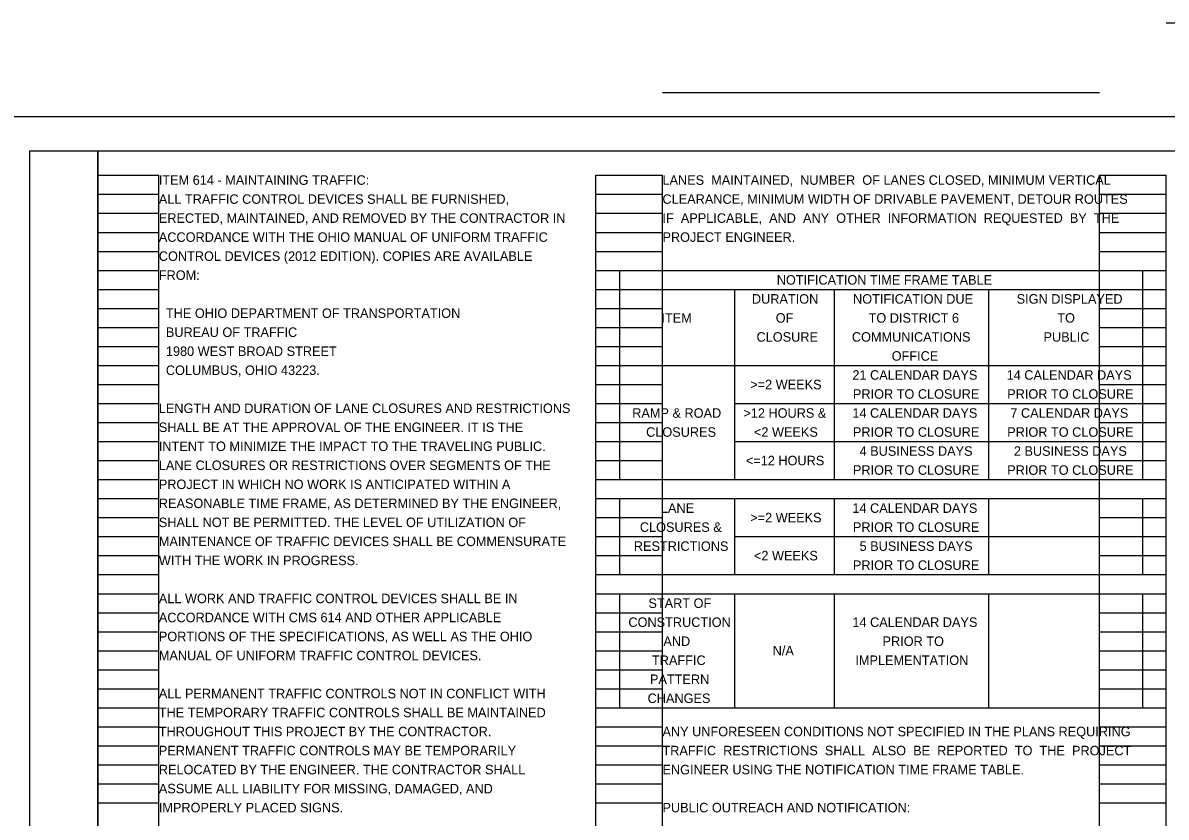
# Model space of a CAD drawing. Extents: x -15.6 to 56.6, y 0 to 56.8.
# Drawn here: x 0.4 to 17.24, y 11.69 to 23.38 of the extents above; entities that cross this region are included whole.
import ezdxf

# ---------------------------------------------------------------- set-up
doc = ezdxf.new("R2010")
doc.units = 0
for name, color, linetype in [('SH_Border', 7, 'Continuous'), ('SH_Cut_Line', 7, 'Continuous'), ('SH_Data', 7, 'Continuous'), ('SH_Text', 7, 'Continuous')]:
    doc.layers.add(name, color=color, linetype=linetype)

msp = doc.modelspace()

# ---------------------------------------------------------------- linework, layer by layer
at = {"layer": 'SH_Border'}
for points in [[(0.5, 21.5), (1.5, 21.5), (1.5, 0.5), (0.5, 0.5)], [(1.5, 21.5), (33.5, 21.5), (33.5, 0.5), (1.5, 0.5)]]:
    msp.add_lwpolyline(points, close=True, dxfattribs=at)
at = {"layer": 'SH_Cut_Line'}
msp.add_lwpolyline([(0, 0), (34, 0), (34, 22), (0, 22)], close=True, dxfattribs=at)
at = {"layer": 'SH_Data'}
for p, q in [((1.5, 0.98), (1.5, 21.14)), ((1.5, 21.14), (2.4, 21.14)), ((2.4, 0.98), (2.4, 21.14)), ((8.84, 0.98), (8.84, 21.14)), ((8.84, 21.14), (9.82, 21.14)), ((9.82, 0.98), (9.82, 21.14)), ((16.26, 0.98), (16.26, 21.14)), ((16.26, 21.14), (17.24, 21.14)), ((17.24, 0.98), (17.24, 21.14)), ((1.5, 20.86), (2.4, 20.86)), ((8.84, 20.86), (9.82, 20.86)), ((16.26, 20.86), (17.24, 20.86)), ((1.5, 20.58), (2.4, 20.58)), ((8.84, 20.58), (9.82, 20.58)), ((16.26, 20.58), (17.24, 20.58)), ((1.5, 20.3), (2.4, 20.3)), ((8.84, 20.3), (9.82, 20.3)), ((16.26, 20.3), (17.24, 20.3)), ((1.5, 20.02), (2.4, 20.02)), ((8.84, 20.02), (9.82, 20.02)), ((16.26, 20.02), (17.24, 20.02)), ((1.5, 19.74), (2.4, 19.74)), ((8.84, 19.74), (9.82, 19.74)), ((16.26, 19.74), (17.24, 19.74)), ((1.5, 19.46), (2.4, 19.46)), ((8.84, 19.46), (9.82, 19.46)), ((16.26, 19.46), (17.24, 19.46)), ((1.5, 19.18), (2.4, 19.18)), ((8.84, 19.18), (9.82, 19.18)), ((16.26, 19.18), (17.24, 19.18)), ((1.5, 18.9), (2.4, 18.9)), ((8.84, 18.9), (9.82, 18.9)), ((16.26, 18.9), (17.24, 18.9)), ((1.5, 18.62), (2.4, 18.62)), ((8.84, 18.62), (9.82, 18.62)), ((16.26, 18.62), (17.24, 18.62)), ((1.5, 18.34), (2.4, 18.34)), ((8.84, 18.34), (9.82, 18.34)), ((16.26, 18.34), (17.24, 18.34)), ((1.5, 18.06), (2.4, 18.06)), ((8.84, 18.06), (9.82, 18.06)), ((16.26, 18.06), (17.24, 18.06)), ((1.5, 17.78), (2.4, 17.78)), ((8.84, 17.78), (9.82, 17.78)), ((16.26, 17.78), (17.24, 17.78)), ((1.5, 17.5), (2.4, 17.5)), ((8.84, 17.5), (9.82, 17.5)), ((16.26, 17.5), (17.24, 17.5)), ((1.5, 17.22), (2.4, 17.22)), ((8.84, 17.22), (9.82, 17.22)), ((16.26, 17.22), (17.24, 17.22)), ((1.5, 16.94), (2.4, 16.94)), ((8.84, 16.94), (9.82, 16.94)), ((16.26, 16.94), (17.24, 16.94)), ((1.5, 16.66), (2.4, 16.66)), ((8.84, 16.66), (9.82, 16.66)), ((16.26, 16.66), (17.24, 16.66)), ((1.5, 16.38), (2.4, 16.38)), ((8.84, 16.38), (9.82, 16.38)), ((16.26, 16.38), (17.24, 16.38)), ((1.5, 16.1), (2.4, 16.1)), ((8.84, 16.1), (9.82, 16.1)), ((16.26, 16.1), (17.24, 16.1)), ((1.5, 15.82), (2.4, 15.82)), ((8.84, 15.82), (9.82, 15.82)), ((16.26, 15.82), (17.24, 15.82)), ((1.5, 15.54), (2.4, 15.54)), ((8.84, 15.54), (9.82, 15.54)), ((16.26, 15.54), (17.24, 15.54)), ((1.5, 15.26), (2.4, 15.26)), ((8.84, 15.26), (9.82, 15.26)), ((16.26, 15.26), (17.24, 15.26)), ((1.5, 14.98), (2.4, 14.98)), ((8.84, 14.98), (9.82, 14.98)), ((16.26, 14.98), (17.24, 14.98)), ((1.5, 14.7), (2.4, 14.7)), ((8.84, 14.7), (9.82, 14.7)), ((16.26, 14.7), (17.24, 14.7)), ((1.5, 14.42), (2.4, 14.42)), ((8.84, 14.42), (9.82, 14.42)), ((16.26, 14.42), (17.24, 14.42)), ((1.5, 14.14), (2.4, 14.14)), ((8.84, 14.14), (9.82, 14.14)), ((16.26, 14.14), (17.24, 14.14)), ((1.5, 13.86), (2.4, 13.86)), ((8.84, 13.86), (9.82, 13.86)), ((16.26, 13.86), (17.24, 13.86)), ((1.5, 13.58), (2.4, 13.58)), ((8.84, 13.58), (9.82, 13.58)), ((16.26, 13.58), (17.24, 13.58)), ((1.5, 13.3), (2.4, 13.3)), ((8.84, 13.3), (9.82, 13.3)), ((16.26, 13.3), (17.24, 13.3)), ((1.5, 13.02), (2.4, 13.02)), ((8.84, 13.02), (9.82, 13.02)), ((16.26, 13.02), (17.24, 13.02)), ((1.5, 12.74), (2.4, 12.74)), ((8.84, 12.74), (9.82, 12.74)), ((16.26, 12.74), (17.24, 12.74)), ((1.5, 12.46), (2.4, 12.46)), ((8.84, 12.46), (9.82, 12.46)), ((16.26, 12.46), (17.24, 12.46)), ((1.5, 12.18), (2.4, 12.18)), ((8.84, 12.18), (9.82, 12.18)), ((16.26, 12.18), (17.24, 12.18)), ((1.5, 11.9), (2.4, 11.9)), ((8.84, 11.9), (9.82, 11.9)), ((16.26, 11.9), (17.24, 11.9))]:
    msp.add_line(p, q, dxfattribs=at)
at = {"layer": 'SH_Text'}
for p, q in [((17.24, 23.384), (23.68, 23.384)), ((9.82, 22.359), (16.26, 22.359)), ((9.186, 19.74), (16.894, 19.74)), ((9.186, 19.74), (9.186, 16.66)), ((16.894, 19.74), (16.894, 16.66)), ((9.186, 19.46), (16.894, 19.46)), ((10.882, 19.46), (10.882, 16.66)), ((12.348, 19.46), (12.348, 16.66)), ((14.621, 19.46), (14.621, 16.66)), ((9.186, 18.34), (16.894, 18.34)), ((10.882, 17.78), (16.894, 17.78)), ((10.882, 17.22), (16.894, 17.22)), ((9.186, 16.66), (16.894, 16.66)), ((9.186, 16.38), (16.894, 16.38)), ((9.186, 16.38), (9.186, 15.26)), ((10.882, 16.38), (10.882, 15.26)), ((12.348, 16.38), (12.348, 15.26)), ((14.621, 16.38), (14.621, 15.26)), ((16.894, 16.38), (16.894, 15.26)), ((10.882, 15.82), (16.894, 15.82)), ((9.186, 15.26), (16.894, 15.26)), ((9.186, 14.98), (16.894, 14.98)), ((9.186, 14.98), (9.186, 13.3)), ((10.882, 14.98), (10.882, 13.3)), ((12.348, 14.98), (12.348, 13.3)), ((14.621, 14.98), (14.621, 13.3)), ((16.894, 14.98), (16.894, 13.3)), ((9.186, 13.3), (16.894, 13.3))]:
    msp.add_line(p, q, dxfattribs=at)

# ---------------------------------------------------------------- texts
for s, p in [('ITEM 614 - MAINTAINING TRAFFIC:', (2.4, 21)), ('LANES  MAINTAINED,  NUMBER  OF LANES CLOSED, MINIMUM VERTICAL', (9.82, 21)), ('ALL TRAFFIC CONTROL DEVICES SHALL BE FURNISHED, ', (2.4, 20.72)), ('CLEARANCE, MINIMUM WIDTH OF DRIVABLE PAVEMENT, DETOUR ROUTES', (9.82, 20.72)), ('ERECTED, MAINTAINED, AND REMOVED BY THE CONTRACTOR IN ', (2.4, 20.44)), ('IF  APPLICABLE,  AND  ANY  OTHER  INFORMATION  REQUESTED  BY  THE', (9.82, 20.44)), ('ACCORDANCE WITH THE OHIO MANUAL OF UNIFORM TRAFFIC ', (2.4, 20.16)), ('PROJECT ENGINEER.', (9.82, 20.16)), ('CONTROL DEVICES (2012 EDITION). COPIES ARE AVAILABLE ', (2.4, 19.88)), ('FROM: ', (2.4, 19.6)), ('NOTIFICATION TIME FRAME TABLE', (11.504, 19.53)), ('DURATION', (11.138, 19.25)), ('NOTIFICATION DUE', (12.628, 19.25)), ('SIGN DISPLAYED', (15.038, 19.25)), ('  THE OHIO DEPARTMENT OF TRANSPORTATION ', (2.4, 19.04)), ('ITEM', (9.805, 18.97)), ('OF', (11.489, 18.97)), ('TO DISTRICT 6', (12.857, 18.97)), ('TO', (15.637, 18.97)), ('  BUREAU OF TRAFFIC', (2.4, 18.76)), ('CLOSURE', (11.206, 18.69)), ('COMMUNICATIONS', (12.611, 18.69)), ('PUBLIC', (15.434, 18.69)), ('  1980 WEST BROAD STREET ', (2.4, 18.48)), (' OFFICE', (13.145, 18.41)), ('  COLUMBUS, OHIO 43223.', (2.4, 18.2)), ('21 CALENDAR DAYS', (12.618, 18.13)), ('14 CALENDAR DAYS', (14.891, 18.13)), ('>=2 WEEKS', (11.113, 17.99)), ('PRIOR TO CLOSURE', (12.626, 17.85)), ('PRIOR TO CLOSURE', (14.899, 17.85)), ('LENGTH AND DURATION OF LANE CLOSURES AND RESTRICTIONS ', (2.4, 17.64)), ('RAMP & ROAD', (9.375, 17.57)), ('>12 HOURS &', (11.012, 17.57)), ('14 CALENDAR DAYS', (12.618, 17.57)), ('7 CALENDAR DAYS', (14.946, 17.57)), ('SHALL BE AT THE APPROVAL OF THE ENGINEER. IT IS THE ', (2.4, 17.36)), ('CLOSURES', (9.579, 17.29)), ('<2 WEEKS', (11.168, 17.29)), ('PRIOR TO CLOSURE', (12.626, 17.29)), ('PRIOR TO CLOSURE', (14.899, 17.29)), ('INTENT TO MINIMIZE THE IMPACT TO THE TRAVELING PUBLIC. ', (2.4, 17.08)), ('<=12 HOURS', (11.049, 16.87)), ('4 BUSINESS DAYS', (12.724, 17.01)), ('2 BUSINESS DAYS', (14.997, 17.01)), ('LANE CLOSURES OR RESTRICTIONS OVER SEGMENTS OF THE ', (2.4, 16.8)), ('PRIOR TO CLOSURE', (12.626, 16.73)), ('PRIOR TO CLOSURE', (14.899, 16.73)), ('PROJECT IN WHICH NO WORK IS ANTICIPATED WITHIN A ', (2.4, 16.52)), ('REASONABLE TIME FRAME, AS DETERMINED BY THE ENGINEER, ', (2.4, 16.24)), ('LANE', (9.797, 16.17)), ('>=2 WEEKS', (11.113, 16.03)), ('14 CALENDAR DAYS', (12.618, 16.17)), ('SHALL NOT BE PERMITTED. THE LEVEL OF UTILIZATION OF ', (2.4, 15.96)), ('CLOSURES &', (9.487, 15.89)), ('PRIOR TO CLOSURE', (12.626, 15.89)), ('MAINTENANCE OF TRAFFIC DEVICES SHALL BE COMMENSURATE ', (2.4, 15.68)), ('RESTRICTIONS', (9.398, 15.61)), ('5 BUSINESS DAYS', (12.724, 15.61)), ('WITH THE WORK IN PROGRESS.', (2.4, 15.4)), ('<2 WEEKS', (11.168, 15.47)), ('PRIOR TO CLOSURE', (12.626, 15.33)), ('ALL WORK AND TRAFFIC CONTROL DEVICES SHALL BE IN ', (2.4, 14.84)), ('START OF', (9.613, 14.77)), ('ACCORDANCE WITH CMS 614 AND OTHER APPLICABLE ', (2.4, 14.56)), ('CONSTRUCTION', (9.318, 14.49)), ('14 CALENDAR DAYS', (12.618, 14.49)), ('PORTIONS OF THE SPECIFICATIONS, AS WELL AS THE OHIO ', (2.4, 14.28)), ('AND', (9.833, 14.21)), ('PRIOR TO', (13.062, 14.21)), ('N/A', (11.444, 14.07)), ('MANUAL OF UNIFORM TRAFFIC CONTROL DEVICES.', (2.4, 14)), ('TRAFFIC', (9.666, 13.93)), ('IMPLEMENTATION', (12.662, 13.93)), ('PATTERN', (9.636, 13.65)), ('ALL PERMANENT TRAFFIC CONTROLS NOT IN CONFLICT WITH ', (2.4, 13.44)), ('CHANGES', (9.601, 13.37)), ('THE TEMPORARY TRAFFIC CONTROLS SHALL BE MAINTAINED ', (2.4, 13.16)), ('THROUGHOUT THIS PROJECT BY THE CONTRACTOR. ', (2.4, 12.88)), ('ANY UNFORESEEN CONDITIONS NOT SPECIFIED IN THE PLANS REQUIRING', (9.82, 12.88)), ('PERMANENT TRAFFIC CONTROLS MAY BE TEMPORARILY ', (2.4, 12.6)), ('TRAFFIC  RESTRICTIONS  SHALL  ALSO  BE  REPORTED  TO  THE  PROJECT', (9.82, 12.6)), ('RELOCATED BY THE ENGINEER. THE CONTRACTOR SHALL ', (2.4, 12.32)), ('ENGINEER USING THE NOTIFICATION TIME FRAME TABLE.', (9.82, 12.32)), ('ASSUME ALL LIABILITY FOR MISSING, DAMAGED, AND ', (2.4, 12.04)), ('IMPROPERLY PLACED SIGNS.', (2.4, 11.76)), ('PUBLIC OUTREACH AND NOTIFICATION:', (9.82, 11.76))]:
    msp.add_text(s, height=0.14, dxfattribs=at).set_placement(p)

doc.saveas('drawing.dxf')
